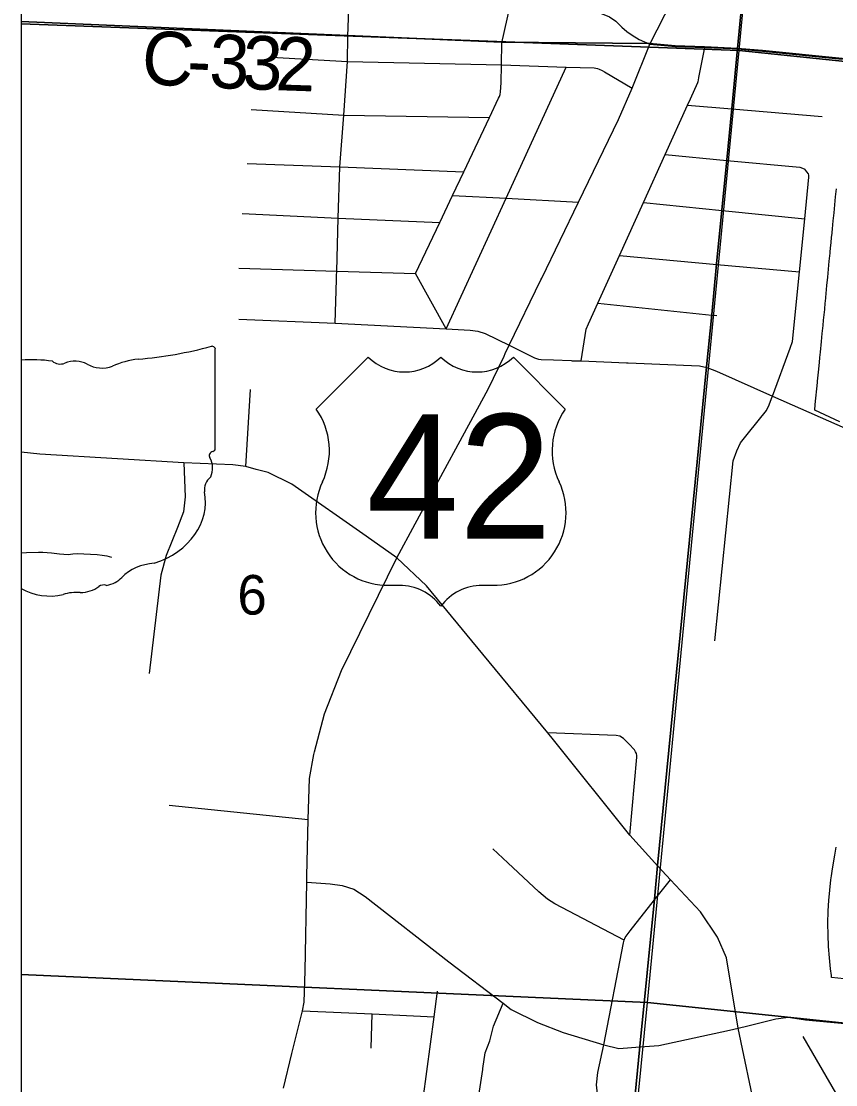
# Model space of a CAD drawing. Extents: x 0 to 34, y -3.9 to 26.2.
# Drawn here: x 2.1 to 2.963, y 16.268 to 17.395 of the extents above; entities that cross this region are included whole.
import ezdxf

# ---------------------------------------------------------------- set-up
doc = ezdxf.new("R2010")
doc.units = 0
for name, color, linetype in [('GM_X_City_Street', 7, 'Continuous'), ('GM_X_Corporation', 7, 'Continuous'), ('GM_X_Corporation_Text', 7, 'Continuous'), ('GM_X_County_Road', 7, 'Continuous'), ('GM_X_County_Road_Text', 7, 'Continuous'), ('GM_X_Interchange_Ramps', 7, 'Continuous'), ('GM_X_Interstate_Route', 7, 'Continuous'), ('GM_X_Minor_River', 7, 'Continuous'), ('GM_X_Section', 7, 'Continuous'), ('GM_X_Section_Text', 7, 'Continuous'), ('GM_X_State_Location', 7, 'Continuous'), ('GM_X_State_Route', 7, 'Continuous'), ('GM_X_State_Shield', 7, 'Continuous'), ('GM_X_US_Location', 7, 'Continuous'), ('GM_X_US_Route', 7, 'Continuous'), ('GM_X_US_Shield', 7, 'Continuous')]:
    doc.layers.add(name, color=color, linetype=linetype)

msp = doc.modelspace()

# ---------------------------------------------------------------- linework, layer by layer
at = {"layer": 'GM_X_City_Street'}
for p, q in [((2.5501, 17.0688), (2.5176, 17.1275)), ((2.3303, 17.0792), (2.4326, 17.075)), ((2.3377, 16.923), (2.3428, 17.0047)), ((2.2565, 16.5644), (2.404, 16.5494)), ((2.4707, 16.307), (2.4716, 16.3433))]:
    msp.add_line(p, q, dxfattribs=at)
for points in [[(2.5176, 17.1275), (2.5432, 17.1814), (2.5568, 17.2102), (2.5687, 17.2354), (2.596, 17.2928), (2.6056, 17.3132), (2.6064, 17.315), (2.6071, 17.3172), (2.6076, 17.32), (2.6082, 17.3295), (2.6085, 17.3485), (2.6089, 17.3718), (2.6177, 17.411)], [(2.3649, 17.3567), (2.4454, 17.3521), (2.6085, 17.3485), (2.6772, 17.3462), (2.7068, 17.3452), (2.7102, 17.3446), (2.7122, 17.3439), (2.7153, 17.3425), (2.7178, 17.3412), (2.747, 17.324)], [(2.8056, 17.3057), (2.8088, 17.3126), (2.8165, 17.3297), (2.8169, 17.3309), (2.8172, 17.3324), (2.8177, 17.3351), (2.8238, 17.367)], [(2.5501, 17.0688), (2.6135, 17.2072), (2.6772, 17.3462)], [(2.3436, 17.3014), (2.4418, 17.2953), (2.596, 17.2928)], [(2.693, 17.0349), (2.6984, 17.0687), (2.7008, 17.0744), (2.7107, 17.0962), (2.7336, 17.1466), (2.7589, 17.2026), (2.7821, 17.2537), (2.8056, 17.3057)], [(2.8056, 17.3057), (2.8527, 17.3018), (2.9483, 17.294)], [(2.3392, 17.2441), (2.4374, 17.2404), (2.5687, 17.2354)], [(2.7821, 17.2537), (2.8474, 17.2474), (2.9245, 17.24), (2.9274, 17.2392), (2.9298, 17.2379)], [(2.8922, 16.9883), (2.8947, 16.9951), (2.8957, 16.9978), (2.9143, 17.0485), (2.9167, 17.0556), (2.9242, 17.1292), (2.9299, 17.1855), (2.9343, 17.2295), (2.9341, 17.2316), (2.9336, 17.233), (2.9319, 17.2352), (2.9298, 17.2379)], [(2.5568, 17.2102), (2.6135, 17.2072), (2.6901, 17.2031)], [(2.7589, 17.2026), (2.8423, 17.1943), (2.9299, 17.1855)], [(2.3341, 17.191), (2.4358, 17.1863), (2.5432, 17.1814)], [(2.7336, 17.1466), (2.8367, 17.1372), (2.9242, 17.1292)], [(2.3304, 17.1333), (2.4342, 17.1301), (2.5176, 17.1275)], [(2.7107, 17.0962), (2.8315, 17.0836), (2.8366, 17.0831)], [(2.8345, 16.7385), (2.8539, 16.929), (2.8579, 16.9399), (2.8619, 16.9481), (2.8702, 16.9589), (2.8894, 16.9823), (2.8922, 16.9883)], [(2.2723, 16.9269), (2.2736, 16.8911), (2.2719, 16.875), (2.2654, 16.8586), (2.2535, 16.8289), (2.2479, 16.8079), (2.2356, 16.7039)], [(2.7444, 16.5327), (2.7521, 16.6152), (2.752, 16.6171), (2.7515, 16.6192), (2.7507, 16.621), (2.7494, 16.6229), (2.7436, 16.6293), (2.7377, 16.6352), (2.7338, 16.6374), (2.7302, 16.6384), (2.6576, 16.6412)], [(2.7386, 16.4214), (2.6652, 16.4598), (2.6574, 16.4649), (2.6481, 16.4728), (2.6152, 16.5035), (2.5995, 16.5182)], [(2.4603, 15.9625), (2.4807, 16.1211), (2.4845, 16.1505), (2.4886, 16.1724), (2.501, 16.204), (2.5229, 16.2452), (2.5257, 16.2534), (2.5372, 16.3404), (2.5407, 16.3674)], [(2.5887, 16.2845), (2.5889, 16.2856), (2.5912, 16.302), (2.5961, 16.3148), (2.6, 16.3303), (2.6103, 16.3546)], [(2.3978, 16.3466), (2.4716, 16.3433), (2.5372, 16.3404)], [(2.9167, 16.1477), (2.9257, 16.1503), (2.9324, 16.1582), (2.9688, 16.2008), (2.9751, 16.2105), (2.9763, 16.2159), (2.9769, 16.2239), (2.9763, 16.2299), (2.9748, 16.2369), (2.9728, 16.2421), (2.928, 16.3196)], [(2.5674, 15.9573), (2.5812, 16.0875), (2.592, 16.1891), (2.5919, 16.192), (2.5917, 16.194), (2.5889, 16.2017), (2.5802, 16.2183), (2.5798, 16.2207), (2.58, 16.2251), (2.5815, 16.2361), (2.5861, 16.266), (2.5887, 16.2845)]]:
    msp.add_lwpolyline(points, dxfattribs=at)
at = {"layer": 'GM_X_Corporation'}
for points in [[(2.9671, 16.9706), (2.9458, 16.9802), (2.9404, 16.9827), (2.941, 16.9887), (2.9432, 17.012), (2.9434, 17.0136), (2.9443, 17.0232), (2.9453, 17.0334), (2.9459, 17.0385), (2.9464, 17.0441), (2.9475, 17.0554), (2.9483, 17.0639), (2.9492, 17.0724), (2.9497, 17.0781), (2.95, 17.0809), (2.9509, 17.0894), (2.9515, 17.0965), (2.9517, 17.098), (2.9525, 17.1065), (2.9533, 17.115), (2.9542, 17.1235), (2.955, 17.1321), (2.9558, 17.1406), (2.9566, 17.1491), (2.9568, 17.1509), (2.9575, 17.1576), (2.9577, 17.16), (2.9583, 17.1661), (2.9587, 17.1699), (2.9588, 17.1709), (2.9591, 17.1747), (2.96, 17.1832), (2.9608, 17.1917), (2.9616, 17.2002), (2.9625, 17.2087), (2.9633, 17.2173)], [(2.9784, 16.3799), (2.9583, 16.3821), (2.9581, 16.384), (2.9572, 16.3913), (2.956, 16.4027), (2.9551, 16.4148), (2.9546, 16.4271), (2.9544, 16.4393), (2.9546, 16.4527), (2.9553, 16.4636), (2.9563, 16.4745), (2.9576, 16.4853), (2.9582, 16.4897), (2.9593, 16.497), (2.9618, 16.5114), (2.9631, 16.52)]]:
    msp.add_lwpolyline(points, dxfattribs=at)
at = {"layer": 'GM_X_Corporation_Text'}
msp.add_line((2.1, 17.0358), (2.1, 16.7941), dxfattribs=at)
msp.add_lwpolyline([(2.3055, 16.9424), (2.3055, 16.9424), (2.3055, 16.9424), (2.3055, 17.0473)], dxfattribs=at)
for centre, major_axis, start_param, end_param in [((2.1881, 17.315), (0.3495, 0), 4.814394, 5.042369), ((2.3019, 17.0475), (0.00367, 0), 6.197627, 7.989034), ((2.111, 16.9298), (0.133, 0), 1.404758, 1.653579), ((2.1412, 17.0402), (0.0107, 0), 3.836095, 5.185415), ((2.1569, 17.017), (0.0222, 0), 0.950623, 2.079405), ((2.1855, 17.0488), (0.0267, 0), 4.08156, 5.145723), ((2.2327, 16.981), (0.0703, 0), 1.699012, 2.107814), ((2.3016, 16.942), (0.00393, 0), 5.054544, 6.418171), ((2.3047, 16.9347), (0.00568, 0), 1.883976, 3.671073), ((2.2686, 16.9215), (0.0341, 0), 5.934695, 6.695948), ((2.3187, 16.8986), (0.0248, 0), 2.387724, 3.262537), ((2.2077, 16.8853), (0.0874, 0), 5.101753, 6.440018), ((2.2446, 16.7824), (0.0479, 0), 1.647645, 2.488434), ((2.1839, 16.8192), (0.0282, 0), 4.937069, 5.64225), ((2.1304, 16.826), (0.0501, 0), 4.061587, 4.996735), ((2.163, 16.8111), (0.0267, 0), 4.691044, 5.507374), ((2.1871, 16.7917), (0.00752, 0), 1.147584, 2.315152), ((2.1593, 16.7569), (0.0412, 0), 1.495662, 1.94098)]:
    msp.add_ellipse(centre, major_axis=major_axis, ratio=0.8, start_param=start_param, end_param=end_param, dxfattribs=at)
at = {"layer": 'GM_X_County_Road'}
for p, q in [((2.8238, 17.367), (2.8529, 17.3657)), ((2.4326, 17.075), (2.4339, 17.1213)), ((2.8694, 16.3306), (2.8991, 16.338))]:
    msp.add_line(p, q, dxfattribs=at)
for points in [[(2.4339, 17.1213), (2.434, 17.125), (2.4342, 17.1301), (2.4358, 17.1863), (2.4374, 17.2404), (2.4418, 17.2953), (2.4454, 17.3521), (2.4459, 17.379), (2.4472, 17.4169)], [(2.6624, 17.4104), (2.6869, 17.4094), (2.7, 17.4074), (2.709, 17.4046), (2.7152, 17.4026), (2.7229, 17.3995), (2.7298, 17.3948), (2.7349, 17.3895), (2.7362, 17.3884)], [(2.7362, 17.3884), (2.7413, 17.3839), (2.7469, 17.3798), (2.7543, 17.3754), (2.7658, 17.3705), (2.7929, 17.3681), (2.8238, 17.367)], [(2.8529, 17.3657), (2.8587, 17.3655), (2.8852, 17.363), (2.9695, 17.3546)], [(2.4326, 17.075), (2.5501, 17.0688), (2.5755, 17.0675), (2.5835, 17.0666), (2.5914, 17.0641), (2.6168, 17.0516)], [(2.6168, 17.0516), (2.6437, 17.0384), (2.6477, 17.0368), (2.6505, 17.0363), (2.6638, 17.036), (2.6823, 17.0353), (2.6833, 17.0352)], [(2.6833, 17.0352), (2.693, 17.0349), (2.741, 17.0329), (2.7429, 17.0328)], [(2.7429, 17.0328), (2.8182, 17.0298), (2.8261, 17.0281), (2.8316, 17.0259), (2.8363, 17.0241), (2.8957, 16.9978), (3.023, 16.9416), (3.0258, 16.941), (3.0268, 16.9408)], [(2.4023, 16.483), (2.4272, 16.4813), (2.4397, 16.4795), (2.4522, 16.4755), (2.4642, 16.4676), (2.5528, 16.3986), (2.6103, 16.3546), (2.619, 16.3479), (2.6469, 16.3344), (2.674, 16.3236), (2.7169, 16.3107), (2.7329, 16.3068), (2.7555, 16.3084)], [(2.7274, 16.0252), (2.7321, 16.0709), (2.7375, 16.124), (2.7411, 16.16), (2.7416, 16.1669), (2.7396, 16.1735), (2.7191, 16.197), (2.7169, 16.2046), (2.7162, 16.2091), (2.7145, 16.2195), (2.7094, 16.2682), (2.7108, 16.2814), (2.7169, 16.3107), (2.7377, 16.4188), (2.7386, 16.4214), (2.7397, 16.4244), (2.7448, 16.4315), (2.7707, 16.4643), (2.7875, 16.4854)], [(2.8991, 16.338), (2.9021, 16.3387), (2.9123, 16.34), (2.9305, 16.337), (3.0292, 16.3278), (3.0322, 16.3275)], [(2.7555, 16.3084), (2.7751, 16.3098), (2.85, 16.3261)], [(2.85, 16.3261), (2.8594, 16.3282), (2.8694, 16.3306)]]:
    msp.add_lwpolyline(points, dxfattribs=at)
at = {"layer": 'GM_X_Interchange_Ramps'}
for points in [[(2.1, 18.7944), (2.1, 15.0478)], [(2.9671, 16.9706), (2.9458, 16.9802), (2.9404, 16.9827), (2.941, 16.9887), (2.9432, 17.012), (2.9434, 17.0136), (2.9443, 17.0232), (2.9453, 17.0334), (2.9459, 17.0385), (2.9464, 17.0441), (2.9475, 17.0554), (2.9483, 17.0639), (2.9492, 17.0724), (2.9497, 17.0781), (2.95, 17.0809), (2.9509, 17.0894), (2.9515, 17.0965), (2.9517, 17.098), (2.9525, 17.1065), (2.9533, 17.115), (2.9542, 17.1235), (2.955, 17.1321), (2.9558, 17.1406), (2.9566, 17.1491), (2.9568, 17.1509), (2.9575, 17.1576), (2.9577, 17.16), (2.9583, 17.1661), (2.9587, 17.1699), (2.9588, 17.1709), (2.9591, 17.1747), (2.96, 17.1832), (2.9608, 17.1917), (2.9616, 17.2002), (2.9625, 17.2087), (2.9633, 17.2173)], [(2.9784, 16.3799), (2.9583, 16.3821), (2.9581, 16.384), (2.9572, 16.3913), (2.956, 16.4027), (2.9551, 16.4148), (2.9546, 16.4271), (2.9544, 16.4393), (2.9546, 16.4527), (2.9553, 16.4636), (2.9563, 16.4745), (2.9576, 16.4853), (2.9582, 16.4897), (2.9593, 16.497), (2.9618, 16.5114), (2.9631, 16.52)]]:
    msp.add_lwpolyline(points, dxfattribs=at)
at = {"layer": 'GM_X_Interstate_Route'}
for points in [[(2.1, 20.9), (2.1, 17.3946), (2.4456, 17.3795), (2.6087, 17.3724), (2.7655, 17.371), (2.7927, 17.3686), (2.8236, 17.3675), (2.8585, 17.366), (2.8647, 17.4286), (2.8852, 17.6093), (2.8923, 17.7142), (2.91, 17.8963), (2.9486, 18.2958)], [(2.9486, 18.2958), (2.91, 17.8963), (2.8923, 17.7142), (2.8852, 17.6093), (2.8647, 17.4286), (2.8585, 17.366), (2.8849, 17.3636), (2.9693, 17.3552), (3.0981, 17.3414), (3.1746, 17.3332), (3.2809, 17.3219), (3.3735, 17.3129), (3.4727, 17.3022), (3.6509, 17.2827), (3.7275, 17.2753), (4.0006, 17.2468), (4.2279, 17.2278), (4.5375, 17.2019), (4.6914, 17.1875), (4.8481, 17.1727)], [(2.7414, 16.1674), (2.7553, 16.3089), (2.7705, 16.4648), (2.774, 16.5005), (2.8259, 17.0286), (2.8313, 17.0842), (2.8365, 17.1377), (2.842, 17.1948), (2.8472, 17.2479), (2.8525, 17.3023), (2.8585, 17.366), (2.8236, 17.3675), (2.7927, 17.3686), (2.7655, 17.371), (2.6087, 17.3724), (2.4456, 17.3795), (2.1, 17.3946), (2.1, 14.1)], [(4.0006, 17.2468), (3.7275, 17.2753), (3.6509, 17.2827), (3.4727, 17.3022), (3.3735, 17.3129), (3.2809, 17.3219), (3.1746, 17.3332), (3.0981, 17.3414), (2.9693, 17.3552), (2.8849, 17.3636), (2.8585, 17.366), (2.8525, 17.3023), (2.8472, 17.2479), (2.842, 17.1948), (2.8365, 17.1377), (2.8313, 17.0842), (2.8259, 17.0286), (2.774, 16.5005), (2.7705, 16.4648), (2.7553, 16.3089), (2.7414, 16.1674)]]:
    msp.add_lwpolyline(points, dxfattribs=at)
at = {"layer": 'GM_X_Minor_River'}
msp.add_lwpolyline([(2.1, 16.8316), (2.1057, 16.8319), (2.1183, 16.8325), (2.1229, 16.8324), (2.1319, 16.8316), (2.1406, 16.8305), (2.1497, 16.8301), (2.1547, 16.8307), (2.1593, 16.8309), (2.1805, 16.83), (2.1858, 16.8294), (2.1907, 16.8284), (2.1956, 16.8271)], dxfattribs=at)
at = {"layer": 'GM_X_Section'}
for points in [[(2.9569, 18.3849), (3.9744, 18.2676), (3.8804, 17.2579), (2.8603, 17.3639)], [(2.8603, 17.3639), (3.8804, 17.2579), (3.7818, 16.2487), (2.7633, 16.3554)], [(2.7633, 16.3554), (3.7818, 16.2487), (3.6849, 15.247), (2.6632, 15.3458)]]:
    msp.add_lwpolyline(points, close=True, dxfattribs=at)
at = {"layer": 'GM_X_State_Route'}
msp.add_line((2.4978, 16.8265), (2.4653, 16.8493), dxfattribs=at)
for points in [[(2.202, 16.9312), (2.1197, 16.9362), (2.1, 16.9384)], [(2.4653, 16.8493), (2.3864, 16.9046), (2.3616, 16.9169), (2.3488, 16.9201), (2.3377, 16.923), (2.3239, 16.925), (2.2723, 16.9269), (2.202, 16.9312)], [(2.589, 16.7243), (2.5291, 16.7967), (2.4978, 16.8265)], [(2.6638, 16.6335), (2.6576, 16.6412), (2.589, 16.7243)], [(2.9199, 16.1384), (2.9167, 16.1477), (2.8878, 16.2059), (2.8786, 16.2358), (2.8594, 16.3282), (2.847, 16.4028), (2.8375, 16.4245), (2.8194, 16.4515), (2.7875, 16.4854), (2.7742, 16.4999), (2.7444, 16.5327), (2.6638, 16.6335)]]:
    msp.add_lwpolyline(points, dxfattribs=at)
at = {"layer": 'GM_X_State_Shield'}
for points in [[(2.1, 18.4182), (2.1, 17.392), (2.8603, 17.3639), (2.9569, 18.3849)], [(2.1, 17.392), (2.1, 16.385), (2.7633, 16.3554), (2.8603, 17.3639)], [(2.1, 16.385), (2.1, 15.3716), (2.6632, 15.3458), (2.7633, 16.3554)]]:
    msp.add_lwpolyline(points, close=True, dxfattribs=at)
at = {"layer": 'GM_X_US_Route'}
for points in [[(2.6512, 17.1227), (2.6901, 17.2031), (2.7325, 17.2907), (2.747, 17.324), (2.7658, 17.3705), (2.8053, 17.4482), (2.8093, 17.4563), (2.8149, 17.468), (2.8587, 17.5592), (2.8854, 17.6088), (2.8986, 17.6334), (2.9396, 17.7194), (2.9564, 17.7524), (2.973, 17.7766), (3.0454, 17.8657)], [(2.6126, 17.0428), (2.6168, 17.0516), (2.6504, 17.121), (2.6512, 17.1227)], [(2.5172, 16.8624), (2.5944, 17.0051), (2.6113, 17.0401), (2.6126, 17.0428)], [(2.4099, 16.6182), (2.4104, 16.6211), (2.4213, 16.6611), (2.4392, 16.707), (2.4978, 16.8265), (2.5172, 16.8624)], [(2.3776, 16.2646), (2.3864, 16.3013), (2.3978, 16.3466), (2.3996, 16.3557), (2.4008, 16.389), (2.4023, 16.483), (2.4024, 16.4894), (2.404, 16.5494), (2.4051, 16.5928), (2.4099, 16.6182)]]:
    msp.add_lwpolyline(points, dxfattribs=at)
at = {"layer": 'GM_X_US_Shield'}
for p, q in [((2.4675, 17.039), (2.4125, 16.984)), ((2.6762, 16.984), (2.6213, 17.039)), ((2.4894, 16.7973), (2.5004, 16.7973)), ((2.5883, 16.7973), (2.5993, 16.7973))]:
    msp.add_line(p, q, dxfattribs=at)
for centre, radius, start, end in [((2.5059, 17.0782), 0.0549, 225.573, 314.427), ((2.5828, 17.0782), 0.0549, 225.573, 314.427), ((2.3495, 16.9399), 0.0769, 334.5471, 35.0009), ((2.7392, 16.9399), 0.0769, 144.9991, 205.4529), ((2.4886, 16.8742), 0.0769, 154.8319, 270.6383), ((2.6001, 16.8742), 0.0769, 269.3617, 25.1681), ((2.5004, 16.7423), 0.0549, 36.8699, 90), ((2.5883, 16.7423), 0.0549, 90, 143.1301)]:
    msp.add_arc(centre, radius, start, end, dxfattribs=at)

# ---------------------------------------------------------------- texts
at = {"layer": 'GM_X_County_Road_Text'}
for s, rotation, p in [('C', 355.3504, (2.2259, 17.3292)), ('3', 357.8579, (2.2984, 17.3243)), ('3', 357.9941, (2.3336, 17.323)), ('2', 358.0109, (2.3686, 17.3218)), ('-', 357.5843, (2.2748, 17.3253))]:
    msp.add_text(s, height=0.0568, rotation=rotation, dxfattribs=at).set_placement(p)
at = {"layer": 'GM_X_Section_Text'}
msp.add_text('6', height=0.0419, rotation=0, dxfattribs=at).set_placement((2.3289, 16.7663))
at = {"layer": 'GM_X_State_Location'}
for s, p in [('s', (2.1371, 16.9253)), ('r', (2.137, 16.9253))]:
    msp.add_text(s, height=0.000189, dxfattribs=at).set_placement(p)
at = {"layer": 'GM_X_US_Location'}
for s in ['0', '/']:
    msp.add_text(s, height=0.000189, dxfattribs=at).set_placement((2.5443, 16.9116))
msp.add_text('42', height=0.000189, rotation=0, dxfattribs=at).set_placement((2.5052, 16.8724))
at = {"layer": 'GM_X_US_Shield'}
msp.add_text('42', height=0.13184, dxfattribs=at).set_placement((2.4656, 16.8467))

doc.saveas('drawing.dxf')
